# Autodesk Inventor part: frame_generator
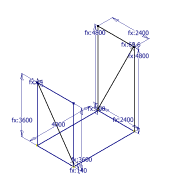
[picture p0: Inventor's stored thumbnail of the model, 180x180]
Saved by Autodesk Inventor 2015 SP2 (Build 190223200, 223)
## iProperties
Created: 2005-09
Part Number: frame_generator
Document SubType Name: Modeling
Designer: hassen
Density: 1 g/cm^3
Material: Generic
Appearance: Default
Author: hassen
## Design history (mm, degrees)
sketch "Sketch1"
  geometry: L1 (0, 0)-(4000, 0); L2 (4000, 0)-(4000, 2400); L3 (4000, 2400)-(0, 2400); L4 (0, 2400)-(0, 0); 1 further point
  constraints: 8 end point, 2 parallel, 1 coincident, 1 horizontal, 1 perpendicular
  dimensions: "base_L" = 4000 distance of L1.start L1.end; "base_W" = 2400 distance of L3.end L1.start (= 0.6 x base_L)
sketch "3D Sketch1" dims "d3" = 4800 (= upright_rear), "d5" = 3600 (= upright_front), "d10" = 100 (= 0.025 x base_L), "d11" = 2400 (= base_W), "d12" = 69.6 (= 0.0174 x base_L), "d13" = 24 (= 0.006 x base_L), "d14" = 140 (= 0.035 x base_L), "upright_rear" = 4800 (= 1.2 x base_L), "upright_front" = 3600 (= 0.9 x base_L)
